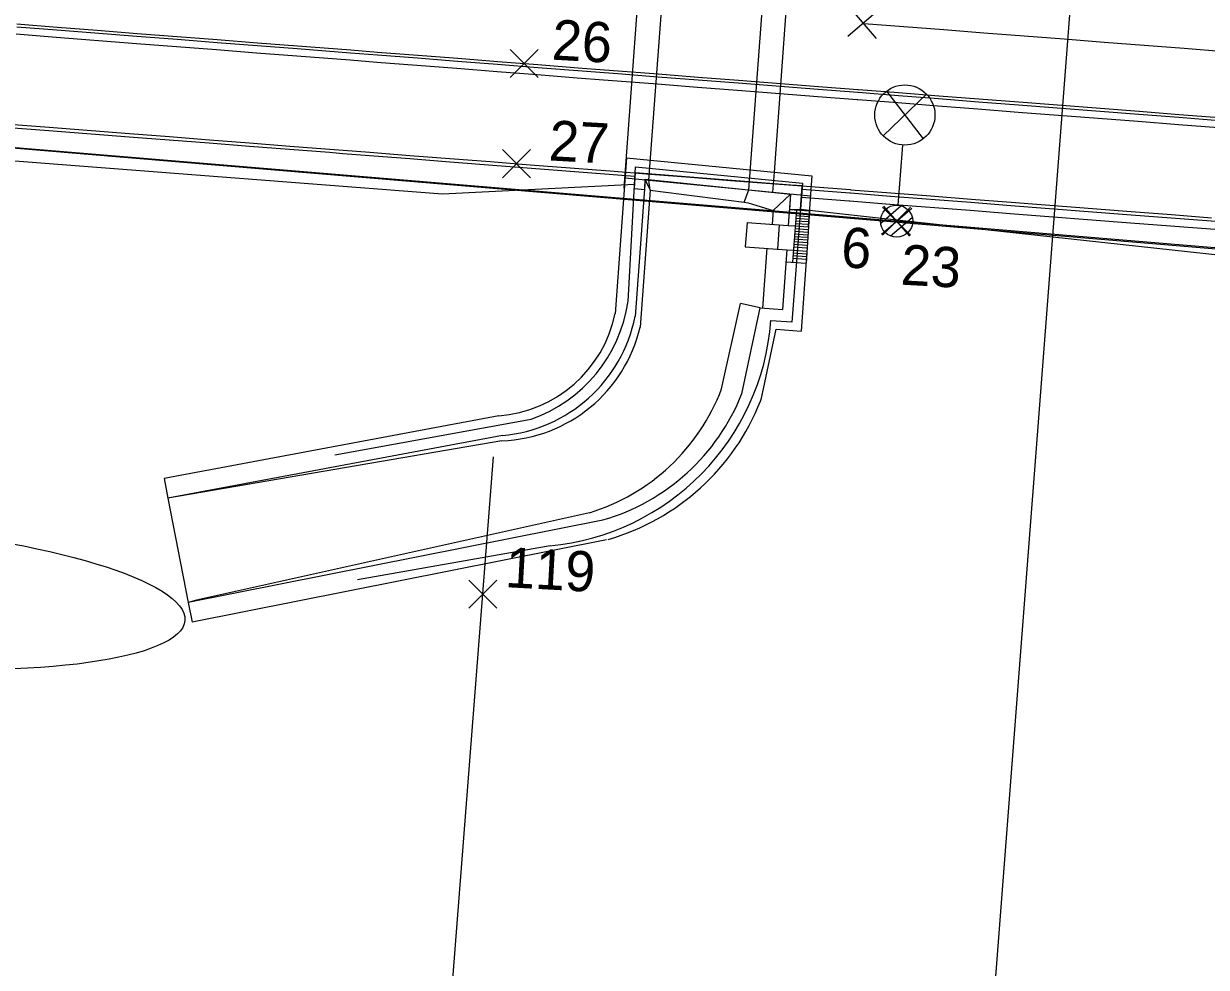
# Model space of a CAD drawing. Extents: x -669661 to -669105, y -977202 to -977030.
# Drawn here: x -669490.51 to -669461.09, y -977169.42 to -977145.95 of the extents above; entities that cross this region are included whole.
import ezdxf

# ---------------------------------------------------------------- set-up
doc = ezdxf.new("R2010")
doc.units = 0
for name, color, linetype in [('CHOD_obrubník', 7, 'Continuous'), ('elektro-EOV', 7, 'Continuous'), ('elektro-osvetleni', 7, 'Continuous'), ('Elektro-VO+EOV', 7, 'Continuous'), ('KN_L_zidky_slabě', 7, 'Continuous'), ('KOL_lomy sklonů', 7, 'Continuous'), ('KOL_osy', 7, 'Continuous'), ('NAST_pudorys', 7, 'Continuous'), ('POP_hlavní popis', 7, 'Continuous'), ('POP_příčné řezy s popisem', 7, 'Continuous'), ('SO 01-20-01', 7, 'Continuous'), ('SO 01-86-01_vytyč_body', 7, 'Continuous'), ('SO 11-10-01_vytyč_body', 7, 'Continuous'), ('SO 11-12-01_vytyč_body', 7, 'Continuous'), ('TER_terén hrany', 7, 'Continuous')]:
    doc.layers.add(name, color=color, linetype=linetype)

# ---------------------------------------------------------------- blocks, each defined once
blk = doc.blocks.new('POINT_DISPLAY')
for p, q in [((-0.35, -0.35), (0.35, 0.35)), ((-0.35, 0.35), (0.35, -0.35))]:
    blk.add_line(p, q)

msp = doc.modelspace()

# ---------------------------------------------------------------- linework, layer by layer
at = {"layer": 'CHOD_obrubník'}
for points in [[(-669498.251, -977147.954), (-669497.86, -977147.984), (-669496.863, -977148.062), (-669495.866, -977148.139), (-669494.869, -977148.217), (-669493.872, -977148.295), (-669492.875, -977148.372), (-669491.878, -977148.45), (-669490.881, -977148.527), (-669489.884, -977148.605), (-669487.89, -977148.76), (-669486.893, -977148.838), (-669485.896, -977148.915), (-669484.899, -977148.993), (-669482.905, -977149.148), (-669482.574, -977149.174), (-669481.908, -977149.226), (-669480.911, -977149.304), (-669479.914, -977149.381), (-669475.307, -977149.74)], [(-669490.875, -977148.448), (-669489.878, -977148.525), (-669487.884, -977148.681), (-669486.887, -977148.758), (-669485.89, -977148.836), (-669484.893, -977148.913), (-669483.896, -977148.991), (-669482.899, -977149.069), (-669482.568, -977149.094), (-669481.902, -977149.146), (-669480.905, -977149.224), (-669479.908, -977149.301), (-669478.911, -977149.379), (-669477.914, -977149.457), (-669476.917, -977149.534), (-669476.261, -977149.585), (-669475.92, -977149.612), (-669474.923, -977149.689), (-669473.926, -977149.767), (-669472.929, -977149.845), (-669470.935, -977150), (-669469.954, -977150.076), (-669469.938, -977150.077), (-669468.941, -977150.155), (-669467.944, -977150.233), (-669466.947, -977150.31), (-669465.951, -977150.388), (-669462.96, -977150.621), (-669461.963, -977150.698), (-669460.966, -977150.776)], [(-669471.15, -977150.063), (-669469.96, -977150.156), (-669469.945, -977150.157), (-669468.948, -977150.235), (-669466.954, -977150.39), (-669465.957, -977150.468), (-669462.966, -977150.7), (-669461.969, -977150.778), (-669460.972, -977150.856), (-669458.978, -977151.011), (-669457.981, -977151.088), (-669456.984, -977151.166), (-669454.99, -977151.321), (-669453.993, -977151.399), (-669451.999, -977151.554), (-669451.002, -977151.632), (-669450.005, -977151.709), (-669449.008, -977151.787), (-669447.014, -977151.942), (-669446.017, -977152.02), (-669445.02, -977152.097), (-669440.956, -977152.414)]]:
    msp.add_lwpolyline(points, dxfattribs=at)
at = {"layer": 'elektro-EOV'}
msp.add_lwpolyline([(-669445.341, -977152.857), (-669517.763, -977146.78), (-669518.507, -977155.699), (-669518.183, -977155.713)], dxfattribs=at)
at = {"layer": 'elektro-osvetleni'}
for p, q in [((-669469.135, -977148.736), (-669468.05, -977147.704)), ((-669469.049, -977147.626), (-669468.137, -977148.813)), ((-669468.651, -977148.966), (-669468.767, -977150.462)), ((-669469.192, -977150.91), (-669468.689, -977150.479)), ((-669468.948, -977151.227), (-669468.411, -977150.767))]:
    msp.add_line(p, q, dxfattribs=at)
msp.add_lwpolyline([(-669445.341, -977152.857), (-669517.763, -977146.78), (-669518.52, -977155.707)], dxfattribs=at)
for centre, radius in [((-669468.593, -977148.22), 0.749), ((-669468.798, -977150.86), 0.4)]:
    msp.add_circle(centre, radius, dxfattribs=at)
at = {"layer": 'Elektro-VO+EOV'}
msp.add_lwpolyline([(-669376.446, -977151.556), (-669386.675, -977150.085), (-669402.797, -977150.85), (-669412.108, -977150.726), (-669421.416, -977150.84), (-669436.037, -977150.686), (-669443.348, -977150.615), (-669443.485, -977152.976), (-669517.763, -977146.78), (-669518.424, -977154.562), (-669518.147, -977154.579)], dxfattribs=at)
at = {"layer": 'KN_L_zidky_slabě'}
for points in [[(-669490.687, -977146.025), (-669489.69, -977146.103), (-669487.696, -977146.258), (-669486.699, -977146.335), (-669485.702, -977146.413), (-669484.705, -977146.491), (-669483.708, -977146.568), (-669482.38, -977146.672), (-669481.714, -977146.723), (-669480.717, -977146.801), (-669479.72, -977146.879), (-669478.723, -977146.956), (-669477.726, -977147.034), (-669476.729, -977147.112), (-669476.073, -977147.163), (-669475.732, -977147.189), (-669474.735, -977147.267), (-669473.738, -977147.344), (-669472.741, -977147.422), (-669470.747, -977147.577), (-669469.766, -977147.654), (-669469.75, -977147.655), (-669468.753, -977147.732), (-669467.756, -977147.81), (-669466.759, -977147.888), (-669465.762, -977147.965), (-669462.771, -977148.198), (-669461.774, -977148.276), (-669460.777, -977148.353)], [(-669490.7, -977146.204), (-669489.704, -977146.282), (-669487.71, -977146.437), (-669486.713, -977146.515), (-669485.716, -977146.593), (-669484.719, -977146.67), (-669483.722, -977146.748), (-669482.725, -977146.825), (-669482.394, -977146.851), (-669481.728, -977146.903), (-669480.731, -977146.981), (-669479.734, -977147.058), (-669478.737, -977147.136), (-669477.74, -977147.213), (-669476.743, -977147.291), (-669476.087, -977147.342), (-669475.746, -977147.369), (-669474.749, -977147.446), (-669473.752, -977147.524), (-669472.755, -977147.601), (-669470.761, -977147.757), (-669469.78, -977147.833), (-669469.764, -977147.834), (-669468.767, -977147.912), (-669467.77, -977147.989), (-669466.773, -977148.067), (-669465.776, -977148.145), (-669462.785, -977148.377), (-669461.788, -977148.455), (-669460.791, -977148.533)]]:
    msp.add_lwpolyline(points, dxfattribs=at)
at = {"layer": 'KOL_lomy sklonů'}
for p, q in [((-669469.252, -977145.614), (-669470.012, -977146.264)), ((-669469.957, -977145.559), (-669469.307, -977146.319))]:
    msp.add_line(p, q, dxfattribs=at)
at = {"layer": 'KOL_osy'}
msp.add_lwpolyline([(-669469.616, -977145.94), (-669468.619, -977146.018), (-669467.622, -977146.095), (-669466.625, -977146.173), (-669465.628, -977146.25), (-669464.631, -977146.328), (-669463.634, -977146.406), (-669462.637, -977146.483), (-669461.641, -977146.561), (-669460.644, -977146.638)], dxfattribs=at)
at = {"layer": 'NAST_pudorys'}
for points in [[(-669490.681, -977145.955), (-669489.684, -977146.033), (-669488.687, -977146.11), (-669487.69, -977146.188), (-669486.693, -977146.266), (-669485.696, -977146.343), (-669484.699, -977146.421), (-669483.702, -977146.498), (-669482.705, -977146.576), (-669482.374, -977146.602), (-669481.708, -977146.654), (-669480.711, -977146.731), (-669479.714, -977146.809), (-669478.717, -977146.887), (-669477.72, -977146.964), (-669476.723, -977147.042), (-669476.067, -977147.093), (-669475.726, -977147.119), (-669474.729, -977147.197), (-669473.732, -977147.275), (-669472.735, -977147.352), (-669470.741, -977147.507), (-669469.76, -977147.584), (-669469.744, -977147.585), (-669468.747, -977147.663), (-669467.75, -977147.74), (-669466.753, -977147.818), (-669465.756, -977147.895), (-669462.766, -977148.128), (-669461.769, -977148.206), (-669460.772, -977148.283)], [(-669471.166, -977150.263), (-669469.976, -977150.355), (-669469.96, -977150.357), (-669468.963, -977150.434), (-669466.969, -977150.589), (-669465.972, -977150.667), (-669462.981, -977150.9), (-669461.984, -977150.977), (-669460.987, -977151.055), (-669458.993, -977151.21), (-669457.996, -977151.288), (-669456.999, -977151.365), (-669455.005, -977151.521), (-669454.008, -977151.598), (-669452.014, -977151.753), (-669451.017, -977151.831), (-669450.02, -977151.909), (-669449.024, -977151.986), (-669447.03, -977152.142), (-669446.033, -977152.219), (-669445.036, -977152.297), (-669443.371, -977152.426)], [(-669471.166, -977150.263), (-669469.976, -977150.355), (-669469.96, -977150.357), (-669468.963, -977150.434), (-669466.969, -977150.589), (-669465.972, -977150.667), (-669462.981, -977150.9), (-669461.984, -977150.977), (-669460.987, -977151.055), (-669458.993, -977151.21), (-669457.996, -977151.288), (-669456.999, -977151.365), (-669455.005, -977151.521), (-669454.008, -977151.598), (-669452.014, -977151.753), (-669451.017, -977151.831), (-669450.02, -977151.909), (-669449.024, -977151.986), (-669447.03, -977152.142), (-669446.033, -977152.219), (-669445.036, -977152.297), (-669443.371, -977152.426)]]:
    msp.add_lwpolyline(points, dxfattribs=at)
msp.add_lwpolyline([(-669475.309, -977149.787), (-669475.324, -977150.051), (-669475.059, -977150.075), (-669475.051, -977149.814), (-669471.439, -977150.187), (-669471.462, -977150.568), (-669471.189, -977150.565), (-669471.144, -977149.984), (-669471.425, -977149.962), (-669475.302, -977149.66)], close=True, dxfattribs=at)
at = {"layer": 'POP_hlavní popis'}
msp.add_line((-669464.325, -977143.44), (-669466.55, -977172.462), dxfattribs=at)
msp.add_ellipse((-669494.386, -977160.177), major_axis=(7.883, -0.614), ratio=0.220603, dxfattribs=at)
at = {"layer": 'POP_příčné řezy s popisem'}
msp.add_lwpolyline([(-669480.837, -977182.602), (-669478.823, -977156.722)], dxfattribs=at)
at = {"layer": 'SO 01-20-01'}
for p, q in [((-669475.576, -977150.04), (-669474.546, -977136.022)), ((-669474.959, -977149.839), (-669473.947, -977136.066)), ((-669472.47, -977150.083), (-669471.452, -977136.221)), ((-669471.836, -977149.643), (-669470.854, -977136.265)), ((-669475.513, -977149.282), (-669475.799, -977153.166)), ((-669475.513, -977149.282), (-669470.904, -977149.735)), ((-669475.478, -977152.855), (-669475.294, -977149.507)), ((-669475.294, -977149.507), (-669471.139, -977149.914)), ((-669471.873, -977150.142), (-669471.836, -977149.643)), ((-669475.55, -977149.781), (-669470.941, -977150.233)), ((-669475.051, -977149.83), (-669475.302, -977153.236)), ((-669475.051, -977149.83), (-669474.928, -977150.089)), ((-669474.928, -977150.089), (-669474.959, -977149.839)), ((-669471.139, -977149.914), (-669471.404, -977153.375)), ((-669470.904, -977149.735), (-669470.998, -977151.003)), ((-669474.928, -977150.089), (-669475.179, -977153.495)), ((-669474.928, -977150.092), (-669472.589, -977150.39)), ((-669472.589, -977150.39), (-669472.47, -977150.083)), ((-669471.87, -977150.593), (-669471.439, -977150.187)), ((-669471.439, -977150.187), (-669471.496, -977150.966)), ((-669472.589, -977150.39), (-669472.494, -977150.405)), ((-669472.494, -977150.405), (-669471.87, -977150.593)), ((-669471.87, -977150.593), (-669471.895, -977150.937)), ((-669471.467, -977150.568), (-669470.968, -977150.604)), ((-669471.29, -977150.581), (-669471.386, -977151.884)), ((-669471.305, -977150.785), (-669470.983, -977150.809)), ((-669471.3, -977150.72), (-669470.979, -977150.744)), ((-669471.295, -977150.655), (-669470.974, -977150.679)), ((-669470.968, -977150.604), (-669471.05, -977151.909)), ((-669472.516, -977150.892), (-669472.561, -977151.497)), ((-669472.516, -977150.892), (-669471.496, -977150.966)), ((-669471.718, -977150.95), (-669471.763, -977151.555)), ((-669471.496, -977150.966), (-669471.319, -977150.979)), ((-669471.329, -977151.109), (-669471.007, -977151.133)), ((-669471.324, -977151.044), (-669471.002, -977151.068)), ((-669471.319, -977150.979), (-669470.998, -977151.003)), ((-669471.315, -977150.915), (-669470.993, -977150.938)), ((-669471.31, -977150.85), (-669470.988, -977150.873)), ((-669471.348, -977151.368), (-669471.026, -977151.392)), ((-669471.343, -977151.304), (-669471.021, -977151.327)), ((-669471.338, -977151.239), (-669471.017, -977151.262)), ((-669471.334, -977151.174), (-669471.012, -977151.198)), ((-669472.561, -977151.497), (-669471.527, -977151.573)), ((-669472.026, -977151.536), (-669472.135, -977153.021)), ((-669471.527, -977151.573), (-669471.636, -977153.058)), ((-669471.527, -977151.573), (-669471.364, -977151.585)), ((-669471.369, -977151.65), (-669471.033, -977151.674)), ((-669471.364, -977151.585), (-669471.028, -977151.609)), ((-669471.357, -977151.498), (-669471.036, -977151.522)), ((-669471.353, -977151.433), (-669471.031, -977151.457)), ((-669471.028, -977151.609), (-669471.174, -977153.593)), ((-669471.549, -977151.872), (-669471.05, -977151.909)), ((-669471.378, -977151.779), (-669471.043, -977151.804)), ((-669471.373, -977151.714), (-669471.038, -977151.739)), ((-669473.152, -977155.031), (-669472.678, -977152.912)), ((-669472.189, -977153.017), (-669472.678, -977152.912)), ((-669472.649, -977155.155), (-669472.189, -977153.017)), ((-669472.189, -977153.017), (-669471.636, -977153.058)), ((-669471.404, -977153.375), (-669471.925, -977153.343)), ((-669472.16, -977155.261), (-669471.792, -977153.548)), ((-669471.792, -977153.548), (-669471.174, -977153.593)), ((-669472.184, -977155.34), (-669472.16, -977155.261)), ((-669478.697, -977155.702), (-669487.016, -977157.264)), ((-669482.773, -977156.673), (-669477.887, -977155.788)), ((-669478.605, -977156.193), (-669486.924, -977157.755)), ((-669478.615, -977156.322), (-669486.924, -977157.755)), ((-669487.016, -977157.264), (-669486.924, -977157.755)), ((-669486.924, -977157.755), (-669486.42, -977160.347)), ((-669476.439, -977158.113), (-669486.218, -977160.292)), ((-669476.109, -977158.295), (-669486.42, -977160.347)), ((-669476.011, -977158.785), (-669486.323, -977160.837)), ((-669477.419, -977158.934), (-669482.209, -977159.783)), ((-669486.218, -977160.292), (-669486.42, -977160.347)), ((-669486.42, -977160.347), (-669486.323, -977160.837))]:
    msp.add_line(p, q, dxfattribs=at)
for centre, radius, start, end in [((-669478.939, -977152.5), 3.211, 274.3323, 348.1321), ((-669478.933, -977152.504), 3.704, 275.1074, 348.7282), ((-669478.75, -977152.656), 3.669, 272.0762, 346.7766), ((-669477.574, -977153.204), 5.298, 286.0891, 338.4449), ((-669477.574, -977153.204), 5.798, 286.0404, 338.4235)]:
    msp.add_arc(centre, radius, start, end, dxfattribs=at)
for centre, major_axis, ratio, start_param, end_param in [((-669479.113, -977152.324), (-0.268, 3.665), 0.999859, 3.40753, 4.494824), ((-669477.988, -977152.881), (5.162, -3.214), 0.99986, 5.361213, 6.765491), ((-669478.008, -977153.148), (3.646, -3.732), 0.9906, 5.811258, 6.713935)]:
    msp.add_ellipse(centre, major_axis=major_axis, ratio=ratio, start_param=start_param, end_param=end_param, dxfattribs=at)
at = {"layer": 'TER_terén hrany'}
for p, q in [((-669497.465, -977148.84), (-669480.094, -977150.182)), ((-669480.094, -977150.182), (-669475.318, -977149.94))]:
    msp.add_line(p, q, dxfattribs=at)
msp.add_lwpolyline([(-669471.189, -977150.565), (-669469.174, -977150.785), (-669453.419, -977152.5), (-669443.371, -977152.426), (-669440.971, -977152.613)], dxfattribs=at)

# ---------------------------------------------------------------- block references
at = {"layer": 'elektro-osvetleni', "rotation": -4.450857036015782}
msp.add_blockref('POINT_DISPLAY', (-669468.798, -977150.86), dxfattribs=at)
at = {"layer": 'SO 01-86-01_vytyč_body'}
msp.add_blockref('POINT_DISPLAY', (-669468.798, -977150.86), dxfattribs=at)
at = {"layer": 'SO 11-10-01_vytyč_body'}
msp.add_blockref('POINT_DISPLAY', (-669479.089, -977160.138), dxfattribs=at)
at = {"layer": 'SO 11-12-01_vytyč_body'}
for p in [(-669478.061, -977146.938), (-669478.255, -977149.43)]:
    msp.add_blockref('POINT_DISPLAY', p, dxfattribs=at)

# ---------------------------------------------------------------- texts
at = {"layer": 'elektro-osvetleni'}
msp.add_text('6', height=1, rotation=356.1, dxfattribs=at).set_placement((-669470.2, -977152))
at = {"layer": 'SO 01-86-01_vytyč_body'}
msp.add_text('23', height=1, rotation=356.8465, dxfattribs=at).set_placement((-669468.711, -977152.438))
at = {"layer": 'SO 11-10-01_vytyč_body'}
msp.add_text('119', height=1, rotation=356.8465, dxfattribs=at).set_placement((-669478.551, -977159.964))
at = {"layer": 'SO 11-12-01_vytyč_body'}
for s, p in [('26', (-669477.392, -977146.841)), ('27', (-669477.466, -977149.348))]:
    msp.add_text(s, height=1, rotation=356.8465, dxfattribs=at).set_placement(p)

doc.saveas('drawing.dxf')
